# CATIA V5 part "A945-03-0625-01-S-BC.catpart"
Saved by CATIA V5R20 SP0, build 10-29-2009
Part number: A945-03-0625-01-S-BC
Source: Unknown
Property "ARTICLENO": "A945-03-0625-01-S-BC"
Property "B": "65.000"
Property "BOMINFO": "A945-03-0625-01-S-BC"
Property "CODE": "A945-03-0625-01-S-BC"
Property "D1": "20.000"
Property "D2": "13.500"
Property "D5": "16.000"
Property "D6": "12.000"
Property "H": "47.000"
Property "H1": "34.000"
Property "H2": "35.000"
Property "H3": "18.000"
Property "L1": "250.000"
Property "L2": "25.000"
Property "L3": "100.000"
Property "L4": "100.000"
Property "L5": "55.000"
Property "L6": "145.000"
Property "LINA": "A945-03-0625-01-S-BC"
Property "N": "3.000"
Property "NB": "A945-03-0625-01-S-BC"
Property "NBSYN": "$CODE."
Property "NN": "A945-03"
Property "NT": "v driver sets replaceable inserts pisitive return"
Property "SUPPLIER": "CF"
Property "Z": "65.000"
Bounding box of the stored display mesh (mm): x -5049.207 to -4951.207, y -575.36 to -510.36, z 0 to 250
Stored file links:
  C:\Users\Utente\Desktop\3D files A945-03\A945-03-0625-01-S-BC.catpart
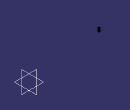
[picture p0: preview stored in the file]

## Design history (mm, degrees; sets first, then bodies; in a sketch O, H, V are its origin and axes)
Body1 "Geometry.1" (main body)
  Solid1 "A945-03-0625-01-S-BC.catpart": solid without history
